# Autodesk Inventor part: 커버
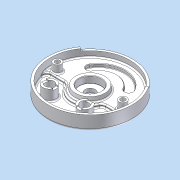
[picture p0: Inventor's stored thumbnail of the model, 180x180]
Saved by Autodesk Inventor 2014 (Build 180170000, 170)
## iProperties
Company: 한국ATC센터
Created: 2015-04
Part Number: 커버
Document SubType Name: Modeling
Designer: KYOUNG IL JANG
Density: 1 g/cm^3
Material: 일반
Mass: 394.015 g
Surface Area: 1019.64 cm^2
Volume: 394.015 cm^3
Appearance: 매끄러움 - 흰색
Author: KYOUNG IL JANG
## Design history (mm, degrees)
sketch "스케치1"
  geometry: L1 (-59, -19)-(-59, 19); L2 (59, 19)-(59, -19); L3 (-41, 19)-(-41, -19); L4 (41, -19)-(41, 19); L5 (38.527, 33.023)-(55.442, 39.179); L6 (-38.527, 33.023)-(-55.442, 39.179); C1 r 90 at (0, 0); C2 r 95 at (0, 0); A1 r 59 centre (0, 19) between (59, 19) and (-59, 19); A2 r 59 centre (0, -19) between (-59, -19) and (59, -19); A3 r 41 centre (0, -19) between (-41, -19) and (41, -19); A4 r 41 centre (0, 19) between (41, 19) and (-41, 19); 2 further points
  constraints: 12 end point, 12 point on circle, 6 centre point, 4 tangent, 2 parallel, 2 point on line, 1 coincident, 1 horizontal alignment, 1 midpoint, 1 vertical, 1 vertical alignment, 3 other
  dimensions: "d2" = 180 diameter of C1; "d3" = 156 dimension on A2 A1; "d4" = 118 distance between parallel lines of L2 L1; "d5" = 18 distance between parallel lines of L2 L4; "d8" = 190 diameter of C2; "d120" = 140 deg angle of L6 L5; "d121" = 110 deg dimension on A1.centre point (0, 0) L5.end
extrude "돌출1" new body sketch "스케치1" distance "d6" = 14; taper "d7" = 0 deg
extrude "돌출2" join sketch "스케치1" distance "d9" = 13; taper "d10" = 0 deg
extrude "돌출3" cut sketch "스케치1" distance "d11" = 7; taper "d12" = 0 deg
sketch "스케치2"
  geometry: C1 r 11.5 at (0, 0); 1 further point
  constraints: 1 centre point, 1 coincident
  dimensions: "d13" = 23 diameter of C1
extrude "돌출4" cut sketch "스케치2" stored distance "d14" = 7; taper "d15" = 0 deg
fillet "모깎기1"
fillet "모깎기2"
sketch "스케치3"
  geometry: L1 (-73.724, 51.622)-(-77.819, 54.49); L2 (73.724, 51.622)-(77.819, 54.49); L3 (0, 0)-(0, -90); A1 r 95 centre (0, 0) between (-77.819, 54.49) and (77.819, 54.49) reference; A2 r 90 centre (0, 0) between (-73.724, 51.622) and (73.724, 51.622) reference; 1 further point
  constraints: 6 end point, 5 point on circle, 1 point on line, 1 vertical, 1 other
  dimensions: "d16" = 250 deg dimension on L2 L1
extrude "돌출5" join sketch "스케치3" distance "d17" = 5; taper "d18" = 0 deg
hole "구멍1" diameter "d21" = 50; stored, may be unused: countersink angle "d25" = 90 deg, drill point angle "d27" = 0 deg; dims "d19" = 10, "d20" = 10, "d22" = 6, "d23" = 4, "d24" = 2, "d26" = 5
fillet "모깎기3" dims "d28" = 0.3
fillet "모깎기5" dims "d30" = 3
sketch "스케치4"
  geometry: C1 r 35 at (0, 0); C2 r 25 at (0, 0); 1 further point
  constraints: 2 centre point, 1 coincident
  dimensions: "d32" = 70 diameter of C1 (derived); "d36" = 10 radial gap between concentric circles of C1 C2
extrude "돌출6" join sketch "스케치4" distance "d33" = 10; taper "d34" = 0 deg
feature "면 기울기2" dims angle "d37" = 10 deg
chamfer "모따기1" distance "d39" = 1; stored, may be unused: second distance "d40" = 2, angle "d41" = 45 deg
fillet "모깎기7" dims "d42" = 5
sketch "스케치5"
  geometry: L1 (-40.249, -12)-(-89.196, -12); L2 (40.249, -12)-(89.196, -12); A1 r 90 centre (0, 0) between (-89.196, -12) and (89.196, -12) reference; A2 r 42 centre (0, 0) between (-40.249, -12) and (40.249, -12); 1 further point
  constraints: 4 end point, 4 point on circle, 1 centre point, 1 collinear, 1 horizontal, 1 point on line
  dimensions: "d43" = 48 radial gap between concentric circles of A1 A2; "d44" = 12 distance from line of point (0, 0) L1
extrude "돌출7" cut sketch "스케치5" stored distance "d45" = 10; taper "d46" = 0 deg
fillet "모깎기8" dims "d47" = 10
chamfer "모따기2" distance "d49" = 1; stored, may be unused: second distance "d50" = 2, angle "d51" = 45 deg
sketch "스케치7"
  geometry: L1 (36.062, 36.062)-(50.912, 50.912); L2 (-36.062, 36.062)-(-50.912, 50.912); A1 r 72 centre (0, 0) between (50.912, 50.912) and (-50.912, 50.912); A2 r 51 centre (0, 0) between (36.062, 36.062) and (-36.062, 36.062); 1 further point
  constraints: 8 point on circle, 4 end point, 2 centre point, 2 point on line, 1 coincident, 1 horizontal alignment
  dimensions: "d54" = 72 radius of A1; "d55" = 21 radial gap between concentric circles of A1 A2; "d56" = 90 deg angle of L2 L1
extrude "돌출8" join sketch "스케치7" distance "d57" = 5; taper "d58" = 0 deg
fillet "모깎기10" dims "d59" = 5
fillet "모깎기11" dims "d60" = 5
fillet "모깎기12" dims "d61" = 3
sketch "스케치6"
  geometry: C1 r 68 at (0, 0); 1 further point
  constraints: 1 centre point, 1 other
  dimensions: "d119" = 136 diameter of C1
feature "엠보싱1" sketch "스케치6" dims "d62" = 0.5, "d63" = 0
sketch "스케치8"
  geometry: C1 r 9 at (74, 0); C2 r 9 at (-74, 0); A1 r 74 centre (0, 0) between (74, 0) and (-74, 0); 1 further point
  constraints: 3 centre point, 2 horizontal alignment, 2 point on circle, 1 coincident, 1 equal radius
  dimensions: "d64" = 18 diameter of C1; "d65" = 148 diameter of A1
extrude "돌출9" join sketch "스케치8" stored distance "d66" = 5; taper "d67" = 0 deg
sketch "스케치11"
  geometry: C1 r 15 at (40, -52); C2 r 15 at (-40, -52); 1 further point
  constraints: 2 centre point, 1 equal radius, 1 horizontal alignment
  dimensions: "d83" = 52 vertical distance of point (0, 0) C1.centre; "d84" = 80 distance of C2.centre C1.centre; "d85" = 40 horizontal distance of point (0, 0) C1.centre (= 0.5 x d84); "d86" = 30 diameter of C1
extrude "돌출10" join sketch "스케치11" stored distance "d87" = 5; taper "d88" = 0 deg
node "구멍3"
node "구멍5"
hole "구멍6" diameter "d93" = 20; stored, may be unused: countersink angle "d97" = 90 deg, drill point angle "d99" = 118 deg; dims "d91" = 10, "d92" = 10, "d94" = 6, "d95" = 4, "d96" = 2, "d98" = 8
hole "구멍7" diameter "d102" = 20; stored, may be unused: countersink angle "d106" = 90 deg, drill point angle "d108" = 118 deg; dims "d100" = 10, "d101" = 10, "d103" = 6, "d104" = 4, "d105" = 2, "d107" = 8
sketch "스케치13"
  geometry: L1 (6, -13.748)-(6, -8); L2 (6, 8)-(6, 13.748); L3 (-6, -13.748)-(-6, -8); L4 (-6, 8)-(-6, 13.748); L5 (-66.252, -6)-(-72, -6); L6 (-88, -6)-(-93.748, -6); L7 (-66.252, 6)-(-72, 6); L8 (-88, 6)-(-93.748, 6); A1 r 15 centre (0, 0) between (6, -13.748) and (6, 13.748) reference; A2 r 10 centre (0, 0) between (6, -8) and (6, 8) reference; A3 r 15 centre (-80, 0) between (-66.252, -6) and (-93.748, -6) reference; A4 r 10 centre (-80, 0) between (-72, -6) and (-88, -6) reference; 1 further point
  constraints: 16 end point, 16 point on circle, 4 equal length, 3 collinear, 2 point on line, 1 perpendicular, 1 vertical
  dimensions: "d109" = 12 distance between parallel lines of L3 L1; "d110" = 6 distance from line of A1.centre L1 (= 0.5 x d109); "d111" = 12 distance between parallel lines of L7 L5; "d112" = 6 distance from line of A3.centre L5 (= 0.5 x d111)
extrude "돌출12" cut sketch "스케치13" distance "d113" = 3; taper "d114" = 0 deg
fillet "모깎기13" dims "d115" = 3
fillet "모깎기14" dims "d116" = 1
node "솔리드1"
sketch "스케치9"
  geometry: 1 further point
hole "구멍2" sketch "스케치9" diameter "d68" = 11; stored, may be unused: countersink angle "d72" = 90 deg, drill point angle "d74" = 0 deg; dims "d69" = 6, "d70" = 18, "d71" = 11, "d73" = 8
sketch "스케치10"
  geometry: 1 further point
hole "구멍4" sketch "스케치10" diameter "d75" = 11; stored, may be unused: countersink angle "d79" = 90 deg, drill point angle "d81" = 0 deg; dims "d76" = 6, "d77" = 18, "d78" = 11, "d80" = 8
